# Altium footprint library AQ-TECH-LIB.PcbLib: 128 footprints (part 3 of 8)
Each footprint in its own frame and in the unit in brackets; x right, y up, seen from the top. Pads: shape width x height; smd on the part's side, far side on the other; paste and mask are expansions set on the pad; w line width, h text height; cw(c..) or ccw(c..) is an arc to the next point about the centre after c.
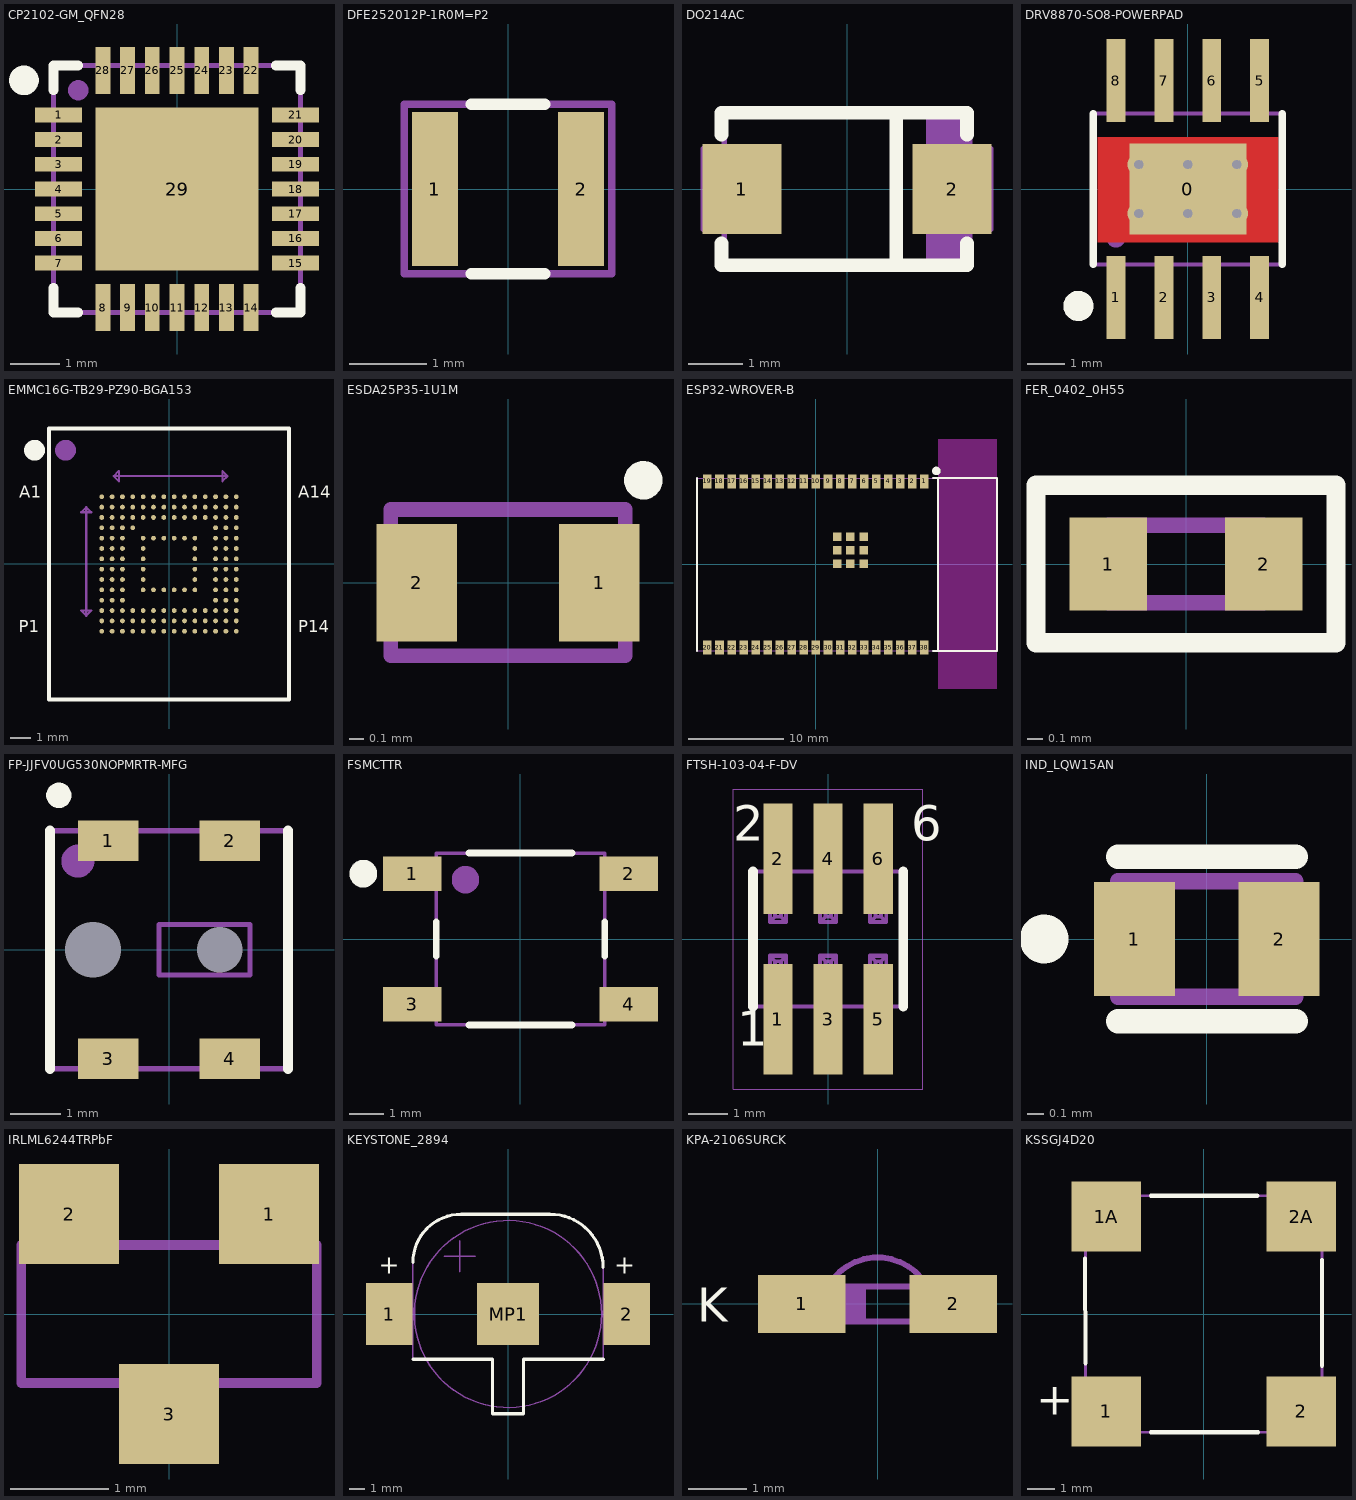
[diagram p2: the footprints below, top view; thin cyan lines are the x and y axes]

## CP2102-GM_QFN28 [mm]
height 1
pads (29):
  rect 0.95x0.3 smd paste+0 mask+0.05: 1(-2.4,1.5) 2(-2.4,1) 3(-2.4,0.5) 4(-2.4,0) 5(-2.4,-0.5) 6(-2.4,-1) 7(-2.4,-1.5) 15(2.4,-1.5) 16(2.4,-1) 17(2.4,-0.5) 18(2.4,0) 19(2.4,0.5) 20(2.4,1) 21(2.4,1.5)
  rect 0.3x0.95 smd paste+0 mask+0.05: 8(-1.5,-2.4) 9(-1,-2.4) 10(-0.5,-2.4) 11(0,-2.4) 12(0.5,-2.4) 13(1,-2.4) 14(1.5,-2.4) 22(1.5,2.4) 23(1,2.4) 24(0.5,2.4) 25(0,2.4) 26(-0.5,2.4) 27(-1,2.4) 28(-1.5,2.4)
  rect 3.3x3.3 smd paste+0 mask+0.1: 29(0,0)
Top Overlay:
  circle w0.4: c-3.1,2.2 r0.1
  lines w0.2: -2.5,-2 -2.5,-2.5 -2,-2.5 ; -2.5,2 -2.5,2.5 -2,2.5 ; 2,-2.5 2.5,-2.5 2.5,-2 ; 2,2.5 2.5,2.5 2.5,2
Mechanical 3:
  region: -2,1.8 -2.04,1.8 -2.113,1.83 -2.17,1.887 -2.2,1.96 -2.2,2.04 -2.17,2.113 -2.113,2.17 -2.04,2.2 -2,2.2 -1.96,2.2 -1.887,2.17 -1.83,2.113 -1.8,2.04 -1.8,1.96 -1.83,1.887 -1.887,1.83 -1.96,1.8
  lines w0.1: -2.5,-2.5 -2.5,2.5 2.5,2.5 2.5,-2.5 -2.5,-2.5
  text ".Designator" at -0.6,0.85 h0.84
3D body: height 1, standoff 0, extent -2.5,-2.5 2.5,2.5
3D body: height 1.01, standoff 0, extent -2.171,1.566 -1.673,2.065

## DFE252012P-1R0M=P2 [mm]
height 1.2
pads (2):
  rect 0.6x2 smd: 1(-0.95,0) 2(0.95,0)
Top Overlay:
  lines w0.15: -0.475,-1.1 0.475,-1.1 ; -0.475,1.1 0.475,1.1
Mechanical 3:
  lines w0.1: -1.35,-1.1 -1.35,1.1 1.35,1.1 1.35,-1.1 -1.35,-1.1
  text ".Designator" at 0.65,0.6 h1
3D body: height 1.2, standoff 0, extent -1.35,-1.1 1.35,1.1

## DO214AC [mm]
height 2.65
pads (2):
  rect 1.45x1.65 smd paste+0 mask+0.1: 1(-1.925,0) 2(1.925,0)
Top Overlay:
  lines w0.25: -2.3,-1 -2.3,-1.4 2.2,-1.4 2.2,-1 ; -2.3,1 -2.3,1.4 2.2,1.4 2.2,1 ; 0.9,-1.3 0.9,1.4
Mechanical 3:
  region: 1.5,-1.39 2.24,-1.39 2.24,1.4 1.5,1.4
  lines w0.1: 1.5,-1.395 1.5,1.395 ; -2.64,-0.735 -2.25,-0.735 -2.25,0.735 -2.64,0.735 -2.64,-0.735 ; -2.25,-1.395 2.25,-1.395 2.25,1.395 -2.25,1.395 -2.25,-1.395 ; 2.25,-0.735 2.25,0.735 2.64,0.735 2.64,-0.735 2.25,-0.735
  text ".Designator" at 0,0 h0.84
3D body "DO214AC(refusion).stp": height 2.4, standoff 0, extent -2.6,-1.3 2.6,1.3

## DRV8870-SO8-POWERPAD [mm]
height 1.7
pads (9):
  rect 3.1x2.4 smd mask+0.1: 0(0,0)
  rect 0.5x2.2 smd mask+0.1: 1(-1.905,-2.875) 2(-0.635,-2.875) 3(0.635,-2.875) 4(1.905,-2.875) 5(1.905,2.875) 6(0.635,2.875) 7(-0.635,2.875) 8(-1.905,2.875)
via 1.3,-0.65 diameter 0.6 hole 0.25
via 1.3,0.65 diameter 0.6 hole 0.25
via 0,0.65 diameter 0.6 hole 0.25
via 0,-0.65 diameter 0.6 hole 0.25
via -1.3,-0.65 diameter 0.6 hole 0.25
via -1.3,0.65 diameter 0.6 hole 0.25
Top Layer:
  rectangle: -2.395,-1.42 2.405,1.38
Top Overlay:
  circle w0.4: c-2.9,-3.1 r0.2
  lines w0.2: -2.5,-2 -2.5,2 ; 2.5,-2 2.5,2
Mechanical 3:
  circle w0.3: c-1.9,-1.3 r0.1
  lines w0.1: -2.5,-2 -2.5,2 2.5,2 2.5,-2 -2.5,-2
  text ".Designator" at 0.9,0.675 h0.84
3D body: height 1.71, standoff 0, extent -2.199,-1.6 -1.601,-1.001
3D body: height 1.7, standoff 0, extent -2.5,-2 2.5,2

## EMMC16G-TB29-PZ90-BGA153 [mm] "BGA153 pas 0.5mm  11.60x13.10mm"
pads (153):
  round 0.23 smd mask+0.075: A1(-3.25,3.25) A2(-2.75,3.25) A3(-2.25,3.25) A4(-1.75,3.25) A5(-1.25,3.25) A6(-0.75,3.25) A7(-0.25,3.25) A8(0.25,3.25) A9(0.75,3.25) A10(1.25,3.25) A11(1.75,3.25) A12(2.25,3.25) A13(2.75,3.25) A14(3.25,3.25) B1(-3.25,2.75) B2(-2.75,2.75) B3(-2.25,2.75) B4(-1.75,2.75) B5(-1.25,2.75) B6(-0.75,2.75) B7(-0.25,2.75) B8(0.25,2.75) B9(0.75,2.75) B10(1.25,2.75) B11(1.75,2.75) B12(2.25,2.75) B13(2.75,2.75) B14(3.25,2.75) C1(-3.25,2.25) C2(-2.75,2.25) C3(-2.25,2.25) C4(-1.75,2.25) C5(-1.25,2.25) C6(-0.75,2.25) C7(-0.25,2.25) C8(0.25,2.25) C9(0.75,2.25) C10(1.25,2.25) C11(1.75,2.25) C12(2.25,2.25) C13(2.75,2.25) C14(3.25,2.25) D1(-3.25,1.75) D2(-2.75,1.75) D3(-2.25,1.75) D4(-1.75,1.75) D12(2.25,1.75) D13(2.75,1.75) D14(3.25,1.75) E1(-3.25,1.25) E2(-2.75,1.25) E3(-2.25,1.25) E5(-1.25,1.25) E6(-0.75,1.25) E7(-0.25,1.25) E8(0.25,1.25) E9(0.75,1.25) E10(1.25,1.25) E12(2.25,1.25) E13(2.75,1.25) E14(3.25,1.25) F1(-3.25,0.75) F2(-2.75,0.75) F3(-2.25,0.75) F5(-1.25,0.75) F10(1.25,0.75) F12(2.25,0.75) F13(2.75,0.75) F14(3.25,0.75) G1(-3.25,0.25) G2(-2.75,0.25) G3(-2.25,0.25) G5(-1.25,0.25) G10(1.25,0.25) G12(2.25,0.25) G13(2.75,0.25) G14(3.25,0.25) H1(-3.25,-0.25) H2(-2.75,-0.25) H3(-2.25,-0.25) H5(-1.25,-0.25) H10(1.25,-0.25) H12(2.25,-0.25) H13(2.75,-0.25) H14(3.25,-0.25) J1(-3.25,-0.75) J2(-2.75,-0.75) J3(-2.25,-0.75) J5(-1.25,-0.75) J10(1.25,-0.75) J12(2.25,-0.75) J13(2.75,-0.75) J14(3.25,-0.75) K1(-3.25,-1.25) K2(-2.75,-1.25) K3(-2.25,-1.25) K5(-1.25,-1.25) K6(-0.75,-1.25) K7(-0.25,-1.25) K8(0.25,-1.25) K9(0.75,-1.25) K10(1.25,-1.25) K12(2.25,-1.25) K13(2.75,-1.25) L1(-3.25,-1.75) l1(3.25,-1.25) L2(-2.75,-1.75) L3(-2.25,-1.75) L12(2.25,-1.75) L13(2.75,-1.75) L14(3.25,-1.75) M1(-3.25,-2.25) M2(-2.75,-2.25) M3(-2.25,-2.25) M4(-1.75,-2.25) M5(-1.25,-2.25) M6(-0.75,-2.25) M7(-0.25,-2.25) M8(0.25,-2.25) M9(0.75,-2.25) M10(1.25,-2.25) M11(1.75,-2.25) M12(2.25,-2.25) M13(2.75,-2.25) M14(3.25,-2.25) N1(-3.25,-2.75) N2(-2.75,-2.75) N3(-2.25,-2.75) N4(-1.75,-2.75) N5(-1.25,-2.75) N6(-0.75,-2.75) N7(-0.25,-2.75) N8(0.25,-2.75) N9(0.75,-2.75) N10(1.25,-2.75) N11(1.75,-2.75) N12(2.25,-2.75) N13(2.75,-2.75) N14(3.25,-2.75) P1(-3.25,-3.25) P2(-2.75,-3.25) P3(-2.25,-3.25) P4(-1.75,-3.25) P5(-1.25,-3.25) P6(-0.75,-3.25) P7(-0.25,-3.25) P8(0.25,-3.25) P9(0.75,-3.25) P10(1.25,-3.25) P11(1.75,-3.25) P12(2.25,-3.25) P13(2.75,-3.25) P14(3.25,-3.25)
Top Overlay:
  circle w0.5: c-6.5,5.5 r0.25
  lines w0.2: -5.8,-6.55 -5.8,6.55 5.8,6.55 5.8,-6.55 -5.8,-6.55
  text "A14" at 6.25,3 h1
  text "P1" at -7.25,-3.5 h1
  text "P14" at 6.25,-3.5 h1
  text "A1" at -7.25,3 h1
Mechanical 3:
  circle w0.5: c-5,5.5 r0.25
  lines w0.1: -4,-2.5 -4.25,-2.25 -3.75,-2.25 -4,-2.5 ; -4,-2.5 -4,2.75 ; -4,2.75 -4.25,2.5 -3.75,2.5 -4,2.75 ; -2.674,4.25 -2.424,4 -2.424,4.5 -2.674,4.25 ; -2.674,4.25 2.826,4.25 ; 2.826,4.25 2.576,4.5 2.576,4 2.826,4.25 ; -5.8,-6.55 -5.8,6.55 5.8,6.55 5.8,-6.55 -5.8,-6.55
  text ".Designator" at 0.45,-0.85 h0.84
  text "P" at -4,-3.25 h0.5
  text "14" at 3.25,4.25 h0.5
  text "A" at -4,3.25 h0.5
  text "1" at -3.25,4.25 h0.5
3D body: height 0.81, standoff 0, extent -5.498,5.001 -4.502,5.999
3D body: height 0.8, standoff 0, extent -5.8,-6.55 5.8,6.55

## ESDA25P35-1U1M [mm]
height 0.6
pads (2):
  rect 0.55x0.8 smd paste+0 mask+0.1: 1(0.625,0) 2(-0.625,0)
Top Overlay:
  circle w0.15: c0.925,0.7 r0.056
Mechanical 3:
  circle w0.15: c0.575,0.225 r0.05
  lines w0.1: -0.8,-0.5 0.8,-0.5 0.8,0.5 -0.8,0.5 -0.8,-0.5
  text ".Designator" at 0,0 h0.84
3D body: height 0.6, standoff 0, extent -0.8,-0.5 0.8,0.5

## ESP32-WROVER-B [mm]
height 3.45
pads (47):
  rect 0.9x1.5 smd paste+0 mask+0.1: 1(11.43,8.75) 2(10.16,8.75) 3(8.89,8.75) 4(7.62,8.75) 5(6.35,8.75) 6(5.08,8.75) 7(3.81,8.75) 8(2.54,8.75) 9(1.27,8.75) 10(0,8.75) 11(-1.27,8.75) 12(-2.54,8.75) 13(-3.81,8.75) 14(-5.08,8.75) 15(-6.35,8.75) 16(-7.62,8.75) 17(-8.89,8.75) 18(-10.16,8.75) 19(-11.43,8.75) 20(-11.43,-8.75) 21(-10.16,-8.75) 22(-8.89,-8.75) 23(-7.62,-8.75) 24(-6.35,-8.75) 25(-5.08,-8.75) 26(-3.81,-8.75) 27(-2.54,-8.75) 28(-1.27,-8.75) 29(0,-8.75) 30(1.27,-8.75) 31(2.54,-8.75) 32(3.81,-8.75) 33(5.08,-8.75) 34(6.35,-8.75) 35(7.62,-8.75) 36(8.89,-8.75) 37(10.16,-8.75) 38(11.43,-8.75)
  rect 0.9x0.9 smd: 39(2.23,0.1) 39(2.23,1.5) 39(2.23,2.9) 39(3.63,0.1) 39(3.63,1.5) 39(3.63,2.9) 39(5.03,0.1) 39(5.03,1.5) 39(5.03,2.9)
Top Overlay:
  circle w0.5: c12.675,9.85 r0.2
  lines w0.2: -12.53,-9.1 -12.53,9.1 ; 12.311,-9.1 12.87,-9.1 ; 12.311,9.1 12.87,9.1 ; 12.87,-9.1 12.87,9.1 ; 12.87,-9.1 19.07,-9.1 19.07,9.1 12.87,9.1
Keep-Out Layer:
  rectangle: 12.87,-13.1 19.07,13.2
Mechanical 3:
  lines w0.1: 19.07,-9.1 19.07,9.1 ; 19.07,-9.1 12.87,-9.1 12.87,9.1 19.07,9.1 ; 19.07,-9.1 19.07,9.1 ; 19.07,-9.1 -12.53,-9.1 -12.53,9.1 19.07,9.1
  text ".Designator" at -0.3,1 h0.84
  text "1" at 11.3,7.5 h1
  text "38" at 10.98,-8.25 h1
  text "20" at -11.88,-8.25 h1
  text "19" at -11.9,7.6 h1
3D body: height 3.45, standoff 0, extent -12.53,-9.1 12.87,9.1
3D body: height 3.45, standoff 2.65, extent 12.87,-9.1 19.07,9.1
3D body: height 3.46, standoff 0, extent 11.004,6.701 12,7.699

## FER_0402_0H55 [mm]
height 0.55
pads (2):
  rect 0.5x0.6 smd: 1(-0.5,0) 2(0.5,0)
Top Overlay:
  lines w0.125: -0.965,-0.508 0.965,-0.508 0.965,0.508 -0.965,0.508 -0.965,-0.508
Mechanical 3:
  lines w0.1: -0.5,-0.25 -0.5,0.25 0.5,0.25 0.5,-0.25 -0.5,-0.25
  text "'.Designator'" at -0.8,-0.075 h1
3D body: height 0.55, standoff 0, extent -0.5,-0.25 0.5,0.25

## FP-JJFV0UG530NOPMRTR-MFG [mm]
pads (6):
  round 0 hole 1.1 unplated mask+0.102: 0(-1.5,0)
  round 0 hole 0.9 unplated mask+0.102: 0(1,0)
  rect 1.2x0.8 smd: 1(-1.2,2.15) 2(1.2,2.15) 3(-1.2,-2.15) 4(1.2,-2.15)
Top Overlay:
  circle w0.25: c-2.175,3.05 r0.125
  lines w0.2: -2.35,-2.35 -2.35,2.35 ; 2.35,-2.35 2.35,2.35
Mechanical 3:
  circle w0.5: c-1.8,1.75 r0.075
  lines w0.1: 1,-0.5 1,0.5 ; -2.35,-2.35 2.35,-2.35 2.35,2.35 -2.35,2.35 -2.35,-2.35 ; -0.2,-0.5 -0.2,0.5 1.6,0.5 1.6,-0.5 -0.2,-0.5
  text ".Designator" at 0,0.188 h1
3D body "Switch_TE_Connectivity_JJFV0UG530NONPRTR_eec.STEP": height 0.25, standoff 0, extent -2.55,-2.65 2.55,2.65

## FSMCTTR [mm]
pads (4):
  rect 1.7x1 smd: 1(-3.15,1.9) 2(3.15,1.9) 3(-3.15,-1.9) 4(3.15,-1.9)
Top Overlay:
  circle w0.5: c-4.575,1.9 r0.152
  lines w0.2: -2.45,-0.5 -2.45,0.5 ; -1.5,-2.5 1.5,-2.5 ; -1.5,2.5 1.5,2.5 ; 2.45,-0.5 2.45,0.5
Mechanical 3:
  circle w0.5: c-1.6,1.725 r0.15
  lines w0.1: -2.45,-2.5 -2.45,2.5 2.45,2.5 2.45,-2.5 -2.45,-2.5
  text ".Designator" at 0,0.188 h1
3D body "FSMCTTR.stp": height 1.6, standoff 0, extent -3.9,-2.5 3.9,2.5

## FTSH-103-04-F-DV [mil]
height 265.75
pads (6):
  rect 29x110 smd: 1(-50,-79.92) 2(-50,79.92) 3(0,-79.92) 4(0,79.92) 5(50,-79.92) 6(50,79.92)
Top Overlay:
  lines w9.84: -75,-67.5 -75,67.5 ; 75,-67.5 75,67.5
  text "2" at -94.49,86.61 h60
  text "1" at -90.55,-118.11 h60
  text "6" at 82.68,86.61 h60
Mechanical 3:
  lines w3.94: -58,-67.5 -58,-115 -42,-115 -42,-67.5 ; -58,67.5 -58,115 -42,115 -42,67.5 ; -42,-32.5 -42,-16.5 -58,-16.5 -58,-17 ; -42,17.5 -42,33.5 -58,33.5 -58,17 ; -8,-67.5 -8,-115 8,-115 8,-67.5 ; -8,67.5 -8,115 8,115 8,67.5 ; 8,-32.5 8,-16.5 -8,-16.5 -8,-17 ; 8,17.5 8,33.5 -8,33.5 -8,33 ; 42,-67.5 42,-115 58,-115 58,-67.5 ; 42,67.5 42,115 58,115 58,67.5 ; 58,-32.5 58,-16.5 42,-16.5 42,-17 ; 58,17.5 58,33.5 42,33.5 42,33 ; -58,-33 -58,-17 ; -58,-33 -52.8,-27.8 ; -58,-33 -42,-33 ; -58,-17 -52.8,-22.2 ; -58,-17 -42,-17 ; -58,17 -42,17 ; -58,17 -52.8,22.2 ; -52.8,-27.8 -52.8,-22.2 ; -52.8,-27.8 -47.2,-27.8 ; -52.8,-22.2 -47.2,-22.2 ; -52.8,22.2 -47.2,22.2 ; -52.8,22.2 -52.8,27.8 ; -52.8,27.8 -58,33 -42,33 ; -52.8,27.8 -47.2,27.8 ; -47.2,-27.8 -42,-33 ; -47.2,-27.8 -47.2,-22.2 ; -47.2,-22.2 -42,-17 ; -47.2,22.2 -47.2,27.8 ; -47.2,22.2 -42,17 ; -47.2,27.8 -42,33 ; -42,-33 -42,-17 ; -42,17 -42,33 ; -8,-33 8,-33 ; -8,-33 -8,-17 ; -8,-33 -2.8,-27.8 ; -8,-17 -2.8,-22.2 ; -8,-17 8,-17 ; -8,17 -8,33 ; -8,17 8,17 ; -8,17 -2.8,22.2 ; -8,33 8,33 ; -8,33 -2.8,27.8 ; -2.8,-27.8 -2.8,-22.2 ; -2.8,-27.8 2.8,-27.8 ; -2.8,-22.2 2.8,-22.2 ; -2.8,22.2 -2.8,27.8 ; -2.8,22.2 2.8,22.2 ; -2.8,27.8 2.8,27.8 ; 2.8,-27.8 8,-33 ; 2.8,-27.8 2.8,-22.2 ; 2.8,-22.2 8,-17 ; 2.8,22.2 8,17 ; 2.8,22.2 2.8,27.8 ; 2.8,27.8 8,33 ; 8,-33 8,-17 ; 8,17 8,33 ; 42,-33 47.2,-27.8 ; 42,-33 42,-17 ; 42,-33 58,-33 ; 42,-17 58,-17 ; 42,-17 47.2,-22.2 ; 42,17 58,17 ; 42,17 47.2,22.2 ; 42,17 42,33 ; 42,33 58,33 ; 42,33 47.2,27.8 ; 47.2,-27.8 47.2,-22.2 ; 47.2,-27.8 52.8,-27.8 ; 47.2,-22.2 52.8,-22.2 ; 47.2,22.2 47.2,27.8 ; 47.2,22.2 52.8,22.2 ; 47.2,27.8 52.8,27.8 ; 52.8,-27.8 58,-33 ; 52.8,-27.8 52.8,-22.2 ; 52.8,-22.2 58,-17 ; 52.8,22.2 58,17 ; 52.8,22.2 52.8,27.8 ; 52.8,27.8 58,33 ; 58,-33 58,-17 ; 58,17 58,33 ; -75,-67.5 -75,67.5 75,67.5 75,-67.5 -75,-67.5
  text "6" at 69.69,90.55 h16.54
  text "2" at -83.86,90.55 h16.54
  text "1" at -79.92,-118.11 h16.54
  text ".Designator" at -91.57,-28.34 h33.07
Mechanical 7:
  lines w0.39: -94.49,-149.61 94.49,-149.61 94.49,149.61 -94.49,149.61 -94.49,-149.61
3D body "FTSH-103-04-F-DV.stp": height 264.75, standoff -0.25, extent -74.99,-114.99 75,115

## IND_LQW15AN [mm]
height 0.6
pads (2):
  rect 0.5x0.7 smd paste+0 mask+0.05: 1(-0.445,0) 2(0.445,0)
Top Overlay:
  circle w0.2: c-1,0 r0.05
  lines w0.15: -0.546,-0.506 0.546,-0.506 ; -0.546,0.506 0.546,0.506
Mechanical 3:
  lines w0.1: -0.546,-0.356 -0.546,0.356 ; -0.546,-0.356 0.546,-0.356 0.546,0.356 -0.546,0.356 ; -0.546,-0.356 -0.3,-0.356 -0.3,0.356 -0.546,0.356 ; -0.546,-0.305 -0.546,0.305 -0.546,-0.305 ; 0.546,-0.305 0.546,0.305 0.546,-0.305
  text ".Designator" at -0.416,-0.03 h0.84
3D body "IND_LQW15AN20NG00D_MUR.step": height 0.61, standoff 0, extent -0.546,-0.356 0.546,0.356

## IRLML6244TRPbF [mil]
height 44.09
pads (3):
  rect 40x40 smd paste+0 mask+3.94: 1(40,40) 2(-40,40) 3(0,-40)
Mechanical 3:
  lines w3.94: -59.1,-27.6 -9.5,-27.6 -9.5,-49.2 9.5,-49.2 9.5,-27.6 59.1,-27.6 59.1,27.6 47,27.6 47,49.2 28,49.2 28,27.6 -28,27.6 -28,49.2 -47,49.2 -47,27.6 -59.1,27.6 -59.1,-27.6
  text ".Designator" at -28,-21.65 h33.07
3D body "Conception1.stp": height 43.31, standoff 0, extent -59.05,-49.21 59.06,49.22

## KEYSTONE_2894 [mm]
height 2.7
pads (3):
  rect 3x4 smd paste+0 mask+0.2: 1(-7.62,0) 2(7.62,0)
  rect 4x4 smd paste+0 mask+0.2: MP1(0,0)
Top Overlay:
  lines w0.2: -6.1,-2.9 -1,-2.9 -1,-6.4 1,-6.4 1,-2.9 6.12,-2.9 ; -6.1,3.3 cw(c-3,3.3) -3,6.4 2.7,6.4 cw(c2.7,3) 6.1,3
  text "+" at -8.3,2.2 h2
  text "+" at 6.8,2.2 h2
Mechanical 3:
  circle w0.1: c0,0 r6
  lines w0.1: -4.1,3.7 -2.1,3.7 ; -3.1,2.7 -3.1,4.7 ; -8.9,-1.6 -6.12,-1.6 -6.12,1.6 -8.9,1.6 -8.9,-1.6 ; -7.62,-0.7 cw(c-7.62,0) -7.62,0.7 cw(c-7.62,0) -7.62,-0.7 ; -6.1,-2.9 -3,-2.9 -1,-2.9 -1,-6.4 1,-6.4 1,-2.9 3.1,-2.9 6.12,-2.9 6.12,3 ccw(c2.72,3) 2.72,6.4 2.7,6.4 -3,6.4 ccw(c-3,3.3) -6.1,3.3 -6.1,-2.9 ; 6.12,-1.6 8.9,-1.6 8.9,1.6 6.12,1.6 6.12,-1.6 ; 7.62,-0.7 cw(c7.62,0) 7.62,0.7 cw(c7.62,0) 7.62,-0.7
  text ".Designator" at -4.299,-0.42 h0.84
3D body: height 0.5, standoff 0, extent -8.9,-1.6 -6.12,1.6
3D body: height 2.2, standoff 0, extent -6,-6 6,6
3D body: height 0.5, standoff 0, extent 6.12,-1.6 8.9,1.6
3D body: height 2.7, standoff 0, extent -6.2,-2.9 -5.8,3.3
3D body: height 2.7, standoff 0, extent 5.9,-2.9 6.3,3
3D body: height 2.7, standoff 2.2, extent -6.1,-6.4 6.12,6.4

## KPA-2106SURCK [mm]
height 0.6
pads (2):
  rect 1.5x1 smd paste+0 mask+0.1: 1(-1.3,0) 2(1.3,0)
Top Overlay:
  text "K" at -3.1,-0.5 h1
Mechanical 3:
  rectangle: -0.85,-0.3 -0.2,0.3
  lines w0.1: -0.85,0.3 cw(c0,-0.172) 0.85,0.3 ; -0.85,0.3 0.85,0.3 ; -0.85,0.3 -0.85,-0.3 0.85,-0.3 0.85,0.3 ; -1.05,-0.3 1.05,-0.3 1.05,0.3 -1.05,0.3 -1.05,-0.3
  text "K" at -1.7,-0.2 h0.42
  text ".Designator" at -1.3,-1.3 h0.84
3D body: height 0.6, standoff 0, extent -1.05,-0.3 1.05,0.3
3D body: height 0.6, standoff 0, extent -0.85,0.3 0.85,0.8
3D body: height 0.61, standoff 0, extent -0.85,-0.3 -0.2,0.3

## KSSGJ4D20 [mm] "BUZZER"
height 3.2
pads (4):
  rect 2.5x2.5 smd paste+0 mask+0.1: 1(-3.5,-3.5) 1A(-3.5,3.5) 2(3.5,-3.5) 2A(3.5,3.5)
Top Overlay:
  lines w0.15: -4.265,1.995 -4.25,-1.77 ; -1.89,-4.25 1.95,-4.25 ; -1.89,4.25 1.92,4.25 ; 4.25,-1.86 4.25,1.935
  text "+" at -6.025,-4.015 h2
Mechanical 3:
  lines w0.1: -4.25,-2.85 -2.85,-4.25 ; -4.25,-2.85 -2.85,-4.25 ; -4.25,-2.85 -4.25,2.85 ; -4.25,2.85 -2.85,4.25 ; -4.25,2.85 -2.85,4.25 ; -2.85,-4.25 2.85,-4.25 ; -2.85,4.25 2.85,4.25 ; 2.85,-4.25 4.25,-2.85 ; 2.85,-4.25 4.25,-2.85 ; 2.85,-4.25 4.25,-2.85 ; 2.85,4.25 4.25,2.85 ; 2.85,4.25 4.25,2.85 ; 4.25,-2.85 4.25,2.85
  text "+" at -3.04,-3.16 h3
  text ".Designator" at 0.29,-0.444 h1
3D body: height 3.2, standoff 0, extent -4.25,-4.25 4.25,4.25
3D body: height 3.21, standoff 0, extent -3.1,-2.9 -1.7,-1.5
